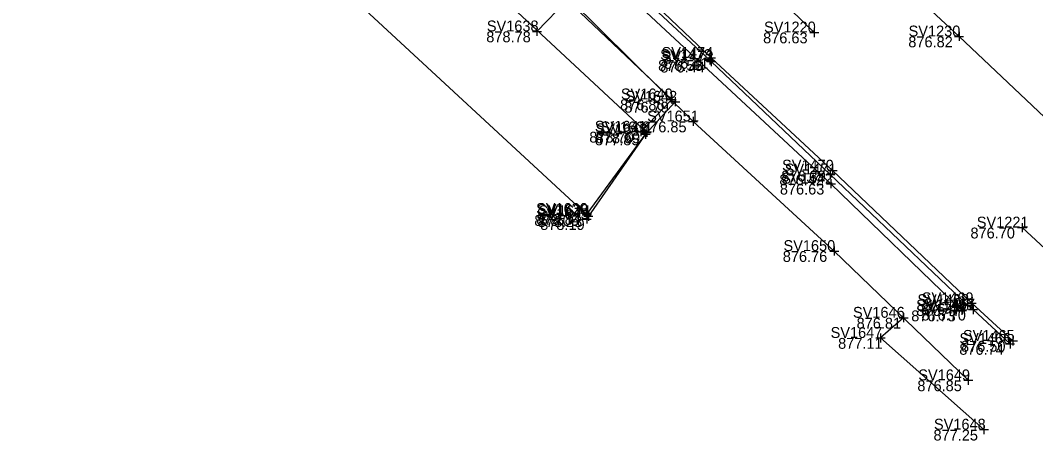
# Model space of a CAD drawing. Extents: x 1480001 to 1480402, y 379235 to 379603.
# Drawn here: x 1480223.3 to 1480335.4, y 379235.4 to 379281.8 of the extents above; entities that cross this region are included whole.
import ezdxf

# ---------------------------------------------------------------- set-up
doc = ezdxf.new("R2010")
doc.units = 0
for name, color, linetype in [('BD_X_Building', 7, 'Continuous'), ('PM_P_CL_Double_Solid', 7, 'Continuous'), ('PM_X_Lane_Line', 7, 'Continuous'), ('PV_X_Curb', 7, 'Continuous'), ('PV_X_Driveway', 7, 'Continuous'), ('PV_X_Steps', 7, 'Continuous'), ('PV_X_Walk', 7, 'Continuous'), ('RD_X_Concrete_Pad', 7, 'Continuous'), ('SV_X_Shot_Marker', 7, 'Continuous'), ('SV_X_Text_Elevation', 7, 'Continuous'), ('SV_X_Text_Name', 7, 'Continuous'), ('UT_X_Water', 7, 'Continuous')]:
    doc.layers.add(name, color=color, linetype=linetype)

msp = doc.modelspace()

# ---------------------------------------------------------------- linework, layer by layer
at = {"layer": 'BD_X_Building'}
msp.add_line((1480254.79, 379289.11), (1480285.84, 379260.34), dxfattribs=at)
at = {"layer": 'PM_P_CL_Double_Solid'}
msp.add_lwpolyline([(1480349.17, 379259.05), (1480326.95, 379280.06), (1480305.57, 379299.92), (1480284.39, 379319.58), (1480263.3, 379339.27), (1480242.58, 379359.21), (1480224.61, 379376.17), (1480208.19, 379391.53)], dxfattribs=at)
at = {"layer": 'PM_X_Lane_Line'}
for p, q in [((1480303.98, 379287.29), (1480310.95, 379280.5)), ((1480333.91, 379258.95), (1480341.1, 379252.27))]:
    msp.add_line(p, q, dxfattribs=at)
at = {"layer": 'PV_X_Curb'}
for points in [[(1480332.57, 379246.1), (1480328.49, 379249.89), (1480327.86, 379250.39), (1480312.73, 379264.82), (1480299.58, 379277.28), (1480299.42, 379277.45), (1480285.03, 379290.83), (1480266.52, 379308.21), (1480264.06, 379310.7), (1480249.54, 379324.24), (1480247.92, 379326.04), (1480238.93, 379334.1), (1480238.59, 379333.85), (1480236.34, 379335.95), (1480234.19, 379337.99), (1480234.33, 379338.21), (1480233.3, 379339.4), (1480215.45, 379356.07)], [(1480332.88, 379246.44), (1480328.34, 379250.59), (1480312.97, 379265.24), (1480299.56, 379277.69), (1480285.41, 379291.2), (1480266.89, 379308.55), (1480264.3, 379310.93), (1480249.8, 379324.51), (1480248.11, 379326.13), (1480239.3, 379334.68), (1480237.07, 379336.68), (1480233.83, 379339.39), (1480215.88, 379356.29)]]:
    msp.add_lwpolyline(points, dxfattribs=at)
at = {"layer": 'PV_X_Driveway'}
for points in [[(1480295.6, 379272.85), (1480292.33, 379269.25), (1480286.02, 379260.2), (1480285.84, 379259.89)], [(1480320.82, 379248.99), (1480318.27, 379246.76), (1480329.69, 379236.63)]]:
    msp.add_lwpolyline(points, dxfattribs=at)
at = {"layer": 'PV_X_Steps'}
msp.add_lwpolyline([(1480280.34, 379280.62), (1480283.66, 379284.09), (1480295.22, 379273.11), (1480291.8, 379269.54)], dxfattribs=at)
at = {"layer": 'PV_X_Walk'}
msp.add_lwpolyline([(1480327.96, 379242.08), (1480313.16, 379256.36), (1480297.58, 379270.67), (1480283.95, 379284.2), (1480267.34, 379299.69), (1480258.51, 379307.78), (1480244.04, 379321.37), (1480229.24, 379335.02), (1480213.41, 379349.98), (1480196.81, 379366.2), (1480192.3, 379370.27), (1480186.39, 379375.8), (1480181.8, 379379.27), (1480179.26, 379381.21), (1480177.45, 379382.13), (1480174.92, 379382.87), (1480171.98, 379383.54), (1480169.49, 379383.4), (1480167.01, 379382.9), (1480162.89, 379380.83), (1480161.3, 379379.69), (1480158.92, 379377.81)], dxfattribs=at)
at = {"layer": 'RD_X_Concrete_Pad'}
msp.add_lwpolyline([(1480285.87, 379260.46), (1480292.46, 379269.46), (1480263.89, 379296.1), (1480254.76, 379289.34)], dxfattribs=at)
at = {"layer": 'SV_X_Shot_Marker'}
for p, q in [((1480280.34, 379281.12), (1480280.34, 379280.12)), ((1480310.95, 379281), (1480310.95, 379280)), ((1480279.84, 379280.62), (1480280.84, 379280.62)), ((1480280.34, 379280.62), (1480280.34, 379280.62)), ((1480310.45, 379280.5), (1480311.45, 379280.5)), ((1480310.95, 379280.5), (1480310.95, 379280.5)), ((1480326.45, 379280.06), (1480327.45, 379280.06)), ((1480326.95, 379280.56), (1480326.95, 379279.56)), ((1480326.95, 379280.06), (1480326.95, 379280.06)), ((1480299.06, 379277.69), (1480300.06, 379277.69)), ((1480299.42, 379277.95), (1480299.42, 379276.95)), ((1480299.56, 379278.19), (1480299.56, 379277.19)), ((1480299.56, 379277.69), (1480299.56, 379277.69)), ((1480299.58, 379277.78), (1480299.58, 379276.78)), ((1480298.92, 379277.45), (1480299.92, 379277.45)), ((1480299.08, 379277.28), (1480300.08, 379277.28)), ((1480299.42, 379277.45), (1480299.42, 379277.45)), ((1480299.58, 379277.28), (1480299.58, 379277.28)), ((1480295.22, 379273.61), (1480295.22, 379272.61)), ((1480295.6, 379273.35), (1480295.6, 379272.35)), ((1480294.72, 379273.11), (1480295.72, 379273.11)), ((1480295.1, 379272.85), (1480296.1, 379272.85)), ((1480295.22, 379273.11), (1480295.22, 379273.11)), ((1480295.6, 379272.85), (1480295.6, 379272.85)), ((1480297.58, 379271.17), (1480297.58, 379270.17)), ((1480291.8, 379270.04), (1480291.8, 379269.04)), ((1480292.33, 379269.75), (1480292.33, 379268.75)), ((1480292.46, 379269.96), (1480292.46, 379268.96)), ((1480297.08, 379270.67), (1480298.08, 379270.67)), ((1480297.58, 379270.67), (1480297.58, 379270.67)), ((1480291.3, 379269.54), (1480292.3, 379269.54)), ((1480291.8, 379269.54), (1480291.8, 379269.54)), ((1480291.83, 379269.25), (1480292.83, 379269.25)), ((1480291.96, 379269.46), (1480292.96, 379269.46)), ((1480292.33, 379269.25), (1480292.33, 379269.25)), ((1480292.46, 379269.46), (1480292.46, 379269.46)), ((1480312.73, 379265.32), (1480312.73, 379264.32)), ((1480312.97, 379265.74), (1480312.97, 379264.74)), ((1480312.23, 379264.82), (1480313.23, 379264.82)), ((1480312.47, 379265.24), (1480313.47, 379265.24)), ((1480312.73, 379264.82), (1480312.73, 379264.82)), ((1480312.8, 379264.3), (1480312.8, 379263.3)), ((1480312.97, 379265.24), (1480312.97, 379265.24)), ((1480312.3, 379263.8), (1480313.3, 379263.8)), ((1480312.8, 379263.8), (1480312.8, 379263.8)), ((1480285.84, 379260.84), (1480285.84, 379259.84)), ((1480285.87, 379260.96), (1480285.87, 379259.96)), ((1480285.34, 379260.34), (1480286.34, 379260.34)), ((1480285.34, 379259.89), (1480286.34, 379259.89)), ((1480285.37, 379260.46), (1480286.37, 379260.46)), ((1480285.52, 379260.2), (1480286.52, 379260.2)), ((1480285.84, 379260.39), (1480285.84, 379259.39)), ((1480285.84, 379260.34), (1480285.84, 379260.34)), ((1480285.84, 379259.89), (1480285.84, 379259.89)), ((1480285.87, 379260.46), (1480285.87, 379260.46)), ((1480286.02, 379260.7), (1480286.02, 379259.7)), ((1480286.02, 379260.2), (1480286.02, 379260.2)), ((1480333.41, 379258.95), (1480334.41, 379258.95)), ((1480333.91, 379259.45), (1480333.91, 379258.45)), ((1480333.91, 379258.95), (1480333.91, 379258.95)), ((1480312.66, 379256.36), (1480313.66, 379256.36)), ((1480313.16, 379256.86), (1480313.16, 379255.86)), ((1480313.16, 379256.36), (1480313.16, 379256.36)), ((1480327.86, 379250.89), (1480327.86, 379249.89)), ((1480328.34, 379251.09), (1480328.34, 379250.09)), ((1480326.76, 379249.8), (1480327.76, 379249.8)), ((1480327.26, 379250.3), (1480327.26, 379249.3)), ((1480327.26, 379249.8), (1480327.26, 379249.8)), ((1480327.36, 379250.39), (1480328.36, 379250.39)), ((1480327.84, 379250.59), (1480328.84, 379250.59)), ((1480327.86, 379250.39), (1480327.86, 379250.39)), ((1480327.99, 379249.89), (1480328.99, 379249.89)), ((1480328.34, 379250.59), (1480328.34, 379250.59)), ((1480328.49, 379250.39), (1480328.49, 379249.39)), ((1480328.49, 379249.89), (1480328.49, 379249.89)), ((1480320.32, 379248.99), (1480321.32, 379248.99)), ((1480320.82, 379249.49), (1480320.82, 379248.49)), ((1480320.82, 379248.99), (1480320.82, 379248.99)), ((1480317.77, 379246.76), (1480318.77, 379246.76)), ((1480318.27, 379247.26), (1480318.27, 379246.26)), ((1480318.27, 379246.76), (1480318.27, 379246.76)), ((1480332.38, 379246.44), (1480333.38, 379246.44)), ((1480332.57, 379246.6), (1480332.57, 379245.6)), ((1480332.88, 379246.94), (1480332.88, 379245.94)), ((1480332.88, 379246.44), (1480332.88, 379246.44)), ((1480332.07, 379246.1), (1480333.07, 379246.1)), ((1480332.57, 379246.1), (1480332.57, 379246.1)), ((1480327.46, 379242.08), (1480328.46, 379242.08)), ((1480327.96, 379242.58), (1480327.96, 379241.58)), ((1480327.96, 379242.08), (1480327.96, 379242.08)), ((1480329.19, 379236.63), (1480330.19, 379236.63)), ((1480329.69, 379237.13), (1480329.69, 379236.13)), ((1480329.69, 379236.63), (1480329.69, 379236.63))]:
    msp.add_line(p, q, dxfattribs=at)
at = {"layer": 'UT_X_Water'}
msp.add_lwpolyline([(1480327.26, 379249.8), (1480312.8, 379263.8), (1480291.92, 379283.18), (1480274.39, 379298.99), (1480265.4, 379307.73), (1480264.5, 379308.46), (1480240.47, 379331.08), (1480234.68, 379335.86), (1480225.09, 379345.6), (1480208.32, 379361.34)], dxfattribs=at)

# ---------------------------------------------------------------- texts
at = {"layer": 'SV_X_Text_Elevation'}
for s, p in [('878.78', (1480274.75, 379279.42)), ('876.63', (1480305.31, 379279.3)), ('876.82', (1480321.34, 379278.86)), ('876.41', (1480294.37, 379276.49)), ('876.56', (1480293.72, 379276.25)), ('876.44', (1480293.96, 379276.08)), ('876.86', (1480289.52, 379271.91)), ('876.79', (1480289.99, 379271.65)), ('876.85', (1480291.95, 379269.47)), ('878.70', (1480286.12, 379268.34)), ('877.85', (1480286.75, 379268.05)), ('878.69', (1480286.83, 379268.26)), ('876.42', (1480307.11, 379263.62)), ('876.39', (1480307.32, 379264.04)), ('876.63', (1480307.16, 379262.6)), ('878.06', (1480280.05, 379259.14)), ('878.84', (1480280.28, 379259.26)), ('878.23', (1480280.43, 379259)), ('878.19', (1480280.7, 379258.69)), ('876.70', (1480328.2, 379257.75)), ('876.76', (1480307.48, 379255.16)), ('876.73', (1480321.66, 379248.6)), ('876.47', (1480322.23, 379249.19)), ('876.44', (1480322.72, 379249.39)), ('876.70', (1480322.79, 379248.69)), ('876.81', (1480315.63, 379247.79)), ('877.11', (1480313.59, 379245.56)), ('876.50', (1480327.16, 379245.24)), ('876.74', (1480326.97, 379244.9)), ('876.85', (1480322.34, 379240.88)), ('877.25', (1480324.12, 379235.43))]:
    msp.add_text(s, height=1.2, dxfattribs=at).set_placement(p)
at = {"layer": 'SV_X_Text_Name'}
for s, p in [('SV1638', (1480274.81, 379280.62)), ('SV1220', (1480305.41, 379280.5)), ('SV1230', (1480321.37, 379280.06)), ('SV1474', (1480294.1, 379277.69)), ('SV1473', (1480293.95, 379277.45)), ('SV1472', (1480294.12, 379277.28)), ('SV1640', (1480289.61, 379273.11)), ('SV1642', (1480290.11, 379272.85)), ('SV1651', (1480292.51, 379270.67)), ('SV1641', (1480286.73, 379269.54)), ('SV1643', (1480286.82, 379269.25)), ('SV1631', (1480287.38, 379269.46)), ('SV1470', (1480307.4, 379265.24)), ('SV1471', (1480307.7, 379264.82)), ('SV1542', (1480307.32, 379263.8)), ('SV1630', (1480280.25, 379260.46)), ('SV1645', (1480280.33, 379259.89)), ('SV1629', (1480280.35, 379260.34)), ('SV1644', (1480280.52, 379260.2)), ('SV1221', (1480328.9, 379258.95)), ('SV1650', (1480307.56, 379256.36)), ('SV1541', (1480322.21, 379249.8)), ('SV1468', (1480322.34, 379250.39)), ('SV1469', (1480322.83, 379250.59)), ('SV1467', (1480322.99, 379249.89)), ('SV1646', (1480315.23, 379248.99)), ('SV1647', (1480312.76, 379246.76)), ('SV1465', (1480327.37, 379246.44)), ('SV1466', (1480326.98, 379246.1)), ('SV1649', (1480322.44, 379242.08)), ('SV1648', (1480324.17, 379236.63))]:
    msp.add_text(s, height=1.2, dxfattribs=at).set_placement(p)

doc.saveas('drawing.dxf')
